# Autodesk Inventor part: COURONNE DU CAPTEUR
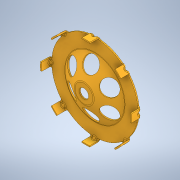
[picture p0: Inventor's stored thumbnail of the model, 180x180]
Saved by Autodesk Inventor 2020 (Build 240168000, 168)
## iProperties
Created: 2003-05
Part Number: COURONNE DU CAPTEUR
Material: Générique
Document SubType Name: Modeling
Designer: Bruno
Density: 1 g/cm^3
Appearance: Par défaut
Author: Bruno
Sending System: SolidWorks 2011
Last Author: Professeur
Last Saved: 2014-11-10
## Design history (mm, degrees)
feature "Répétition circulaire2"
node "Solide1"
